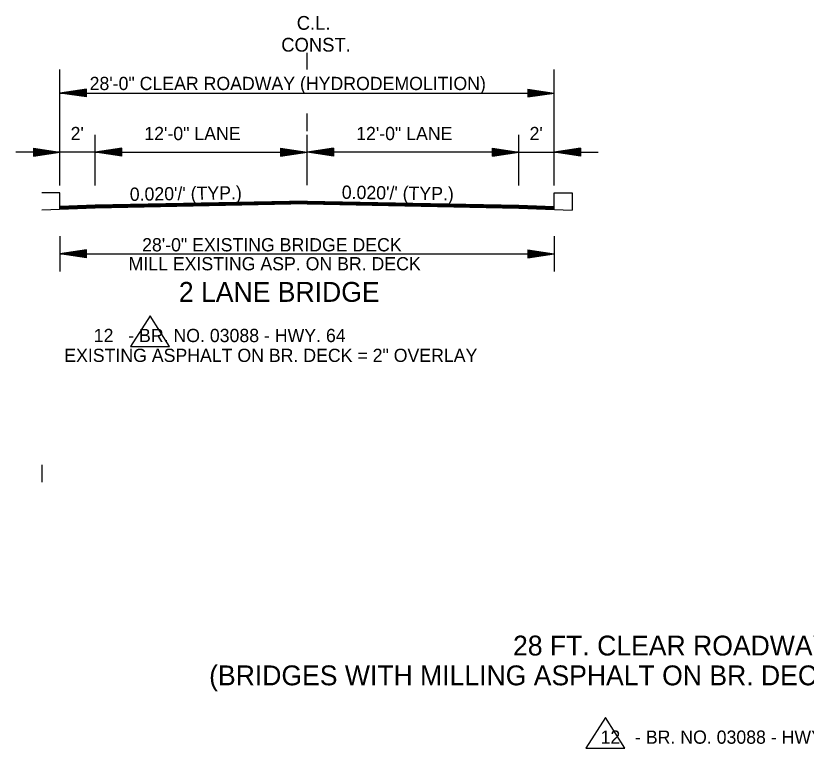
# Model space of a CAD drawing. Extents: x 542112 to 1930787, y -1968972 to 596640.
# Drawn here: x 544325.2 to 544772.9, y -1957025.2 to -1956610.4 of the extents above; entities that cross this region are included whole.
import ezdxf

# ---------------------------------------------------------------- set-up
doc = ezdxf.new("R2010")
doc.units = 0
doc.layers.add('R_Border', color=7, linetype='Continuous')
doc.layers.add('R_Draft', color=7, linetype='Continuous')

msp = doc.modelspace()

# ---------------------------------------------------------------- linework, layer by layer
at = {"layer": 'R_Border'}
for p, q in [((544350.18, -1956710.76), (544340.02, -1956710.76)), ((544350.18, -1956720.17), (544350.18, -1956710.76)), ((544630.18, -1956720.17), (544630.18, -1956710.76)), ((544630.18, -1956710.76), (544640.35, -1956710.76)), ((544640.35, -1956710.76), (544640.35, -1956720.57)), ((544401.25, -1956780.4), (544390.21, -1956797.7)), ((544412.29, -1956797.7), (544401.25, -1956780.4)), ((544390.21, -1956797.7), (544412.29, -1956797.7)), ((544340.02, -1956864.65), (544340.02, -1956874.46)), ((544659.17, -1957007.87), (544648.13, -1957025.17)), ((544670.21, -1957025.17), (544659.17, -1957007.87)), ((544648.13, -1957025.17), (544670.21, -1957025.17))]:
    msp.add_line(p, q, dxfattribs=at)
at = {"layer": 'R_Draft'}
for p, q in [((544490.18, -1956640.74), (544490.18, -1956631.43)), ((544350.18, -1956706.52), (544350.18, -1956640.78)), ((544630.18, -1956706.52), (544630.18, -1956640.78)), ((544365.18, -1956651.9), (544350.18, -1956654.15)), ((544350.18, -1956654.15), (544630.18, -1956654.15)), ((544365.18, -1956656.4), (544350.18, -1956654.15)), ((544365.18, -1956652.28), (544352.69, -1956654.15)), ((544365.18, -1956656.03), (544352.69, -1956654.15)), ((544365.18, -1956652.66), (544355.27, -1956654.15)), ((544365.18, -1956655.65), (544355.27, -1956654.15)), ((544365.18, -1956653.04), (544357.77, -1956654.15)), ((544365.18, -1956655.27), (544357.77, -1956654.15)), ((544365.18, -1956653.42), (544360.31, -1956654.15)), ((544365.18, -1956654.88), (544360.31, -1956654.15)), ((544365.18, -1956653.8), (544362.81, -1956654.15)), ((544365.18, -1956654.51), (544362.81, -1956654.15)), ((544365.18, -1956656.4), (544365.18, -1956651.9)), ((544615.18, -1956651.9), (544630.18, -1956654.15)), ((544615.18, -1956651.9), (544615.18, -1956656.4)), ((544615.18, -1956652.28), (544627.68, -1956654.15)), ((544615.18, -1956652.66), (544625.1, -1956654.15)), ((544615.18, -1956653.04), (544622.6, -1956654.15)), ((544615.18, -1956653.43), (544620.06, -1956654.15)), ((544615.18, -1956653.8), (544617.55, -1956654.15)), ((544615.18, -1956656.4), (544630.18, -1956654.15)), ((544615.18, -1956654.89), (544620.06, -1956654.15)), ((544615.18, -1956655.65), (544625.1, -1956654.15)), ((544615.18, -1956656.03), (544627.68, -1956654.15)), ((544615.18, -1956655.27), (544622.6, -1956654.15)), ((544615.18, -1956654.51), (544617.55, -1956654.15)), ((544490.18, -1956675.67), (544490.18, -1956665.8)), ((544370.18, -1956706.52), (544370.18, -1956677.8)), ((544490.18, -1956706.35), (544490.18, -1956677.8)), ((544610.18, -1956706.52), (544610.18, -1956677.8)), ((544335.18, -1956685.44), (544350.18, -1956687.69)), ((544335.18, -1956685.44), (544335.18, -1956689.94)), ((544335.18, -1956685.82), (544347.68, -1956687.69)), ((544385.18, -1956685.44), (544370.18, -1956687.69)), ((544385.18, -1956685.82), (544372.69, -1956687.69)), ((544385.18, -1956689.94), (544385.18, -1956685.44)), ((544475.18, -1956685.44), (544490.18, -1956687.69)), ((544475.18, -1956685.44), (544475.18, -1956689.94)), ((544475.18, -1956685.82), (544487.68, -1956687.69)), ((544505.18, -1956685.44), (544490.18, -1956687.69)), ((544505.18, -1956685.82), (544492.69, -1956687.69)), ((544505.18, -1956685.44), (544505.18, -1956689.94)), ((544595.18, -1956685.44), (544610.18, -1956687.69)), ((544595.18, -1956689.94), (544595.18, -1956685.44)), ((544595.18, -1956685.82), (544607.68, -1956687.69)), ((544645.18, -1956685.44), (544630.18, -1956687.69)), ((544645.18, -1956685.82), (544632.69, -1956687.69)), ((544645.18, -1956685.44), (544645.18, -1956689.94)), ((544350.18, -1956687.69), (544325.18, -1956687.69)), ((544335.18, -1956686.2), (544345.1, -1956687.69)), ((544335.18, -1956686.57), (544342.6, -1956687.69)), ((544335.18, -1956686.96), (544340.06, -1956687.69)), ((544335.18, -1956687.34), (544337.55, -1956687.69)), ((544335.18, -1956689.94), (544350.18, -1956687.69)), ((544335.18, -1956688.43), (544340.06, -1956687.69)), ((544335.18, -1956689.18), (544345.1, -1956687.69)), ((544335.18, -1956689.57), (544347.68, -1956687.69)), ((544335.18, -1956688.81), (544342.6, -1956687.69)), ((544335.18, -1956688.04), (544337.55, -1956687.69)), ((544370.18, -1956687.69), (544350.18, -1956687.69)), ((544385.18, -1956689.94), (544370.18, -1956687.69)), ((544370.18, -1956687.69), (544490.18, -1956687.69)), ((544385.18, -1956689.57), (544372.69, -1956687.69)), ((544385.18, -1956686.2), (544375.27, -1956687.69)), ((544385.18, -1956689.18), (544375.27, -1956687.69)), ((544385.18, -1956686.57), (544377.77, -1956687.69)), ((544385.18, -1956688.81), (544377.77, -1956687.69)), ((544385.18, -1956686.96), (544380.31, -1956687.69)), ((544385.18, -1956688.42), (544380.31, -1956687.69)), ((544385.18, -1956687.34), (544382.81, -1956687.69)), ((544385.18, -1956688.04), (544382.81, -1956687.69)), ((544475.18, -1956686.2), (544485.1, -1956687.69)), ((544475.18, -1956686.57), (544482.6, -1956687.69)), ((544475.18, -1956686.96), (544480.06, -1956687.69)), ((544475.18, -1956687.34), (544477.55, -1956687.69)), ((544475.18, -1956689.94), (544490.18, -1956687.69)), ((544475.18, -1956688.43), (544480.06, -1956687.69)), ((544475.18, -1956689.18), (544485.1, -1956687.69)), ((544475.18, -1956689.57), (544487.68, -1956687.69)), ((544475.18, -1956688.81), (544482.6, -1956687.69)), ((544475.18, -1956688.04), (544477.55, -1956687.69)), ((544610.18, -1956687.69), (544490.18, -1956687.69)), ((544505.18, -1956689.94), (544490.18, -1956687.69)), ((544505.18, -1956689.57), (544492.69, -1956687.69)), ((544505.18, -1956686.2), (544495.27, -1956687.69)), ((544505.18, -1956689.18), (544495.27, -1956687.69)), ((544505.18, -1956686.57), (544497.77, -1956687.69)), ((544505.18, -1956688.81), (544497.77, -1956687.69)), ((544505.18, -1956686.96), (544500.31, -1956687.69)), ((544505.18, -1956688.43), (544500.31, -1956687.69)), ((544505.18, -1956687.34), (544502.81, -1956687.69)), ((544505.18, -1956688.04), (544502.81, -1956687.69)), ((544595.18, -1956686.2), (544605.1, -1956687.69)), ((544595.18, -1956686.57), (544602.6, -1956687.69)), ((544595.18, -1956686.96), (544600.06, -1956687.69)), ((544595.18, -1956687.34), (544597.55, -1956687.69)), ((544595.18, -1956689.94), (544610.18, -1956687.69)), ((544595.18, -1956688.42), (544600.06, -1956687.69)), ((544595.18, -1956689.18), (544605.1, -1956687.69)), ((544595.18, -1956689.57), (544607.68, -1956687.69)), ((544595.18, -1956688.81), (544602.6, -1956687.69)), ((544595.18, -1956688.04), (544597.55, -1956687.69)), ((544610.18, -1956687.69), (544630.18, -1956687.69)), ((544645.18, -1956689.94), (544630.18, -1956687.69)), ((544630.18, -1956687.69), (544655.18, -1956687.69)), ((544645.18, -1956689.57), (544632.69, -1956687.69)), ((544645.18, -1956686.2), (544635.27, -1956687.69)), ((544645.18, -1956689.18), (544635.27, -1956687.69)), ((544645.18, -1956686.57), (544637.77, -1956687.69)), ((544645.18, -1956688.81), (544637.77, -1956687.69)), ((544645.18, -1956686.96), (544640.31, -1956687.69)), ((544645.18, -1956688.43), (544640.31, -1956687.69)), ((544645.18, -1956687.34), (544642.81, -1956687.69)), ((544645.18, -1956688.04), (544642.81, -1956687.69)), ((544490.18, -1956715.3), (544370.18, -1956717.7)), ((544490.19, -1956715.6), (544370.18, -1956718)), ((544490.2, -1956715.9), (544370.18, -1956718.3)), ((544490.2, -1956716.2), (544370.18, -1956718.6)), ((544490.21, -1956716.5), (544370.18, -1956718.9)), ((544490.21, -1956716.8), (544370.18, -1956719.2)), ((544490.22, -1956716.97), (544370.18, -1956719.37)), ((544490.15, -1956716.8), (544610.18, -1956719.2)), ((544490.15, -1956716.97), (544610.18, -1956719.37)), ((544490.16, -1956716.5), (544610.18, -1956718.9)), ((544490.17, -1956715.9), (544610.18, -1956718.3)), ((544490.17, -1956716.2), (544610.18, -1956718.6)), ((544490.18, -1956715.3), (544610.18, -1956717.7)), ((544490.18, -1956715.6), (544610.18, -1956718)), ((544370.18, -1956719.37), (544340.02, -1956720.57)), ((544370.18, -1956717.7), (544350.18, -1956718.5)), ((544370.18, -1956718), (544350.18, -1956718.8)), ((544370.18, -1956718.3), (544350.18, -1956719.1)), ((544370.18, -1956718.6), (544350.18, -1956719.4)), ((544370.18, -1956718.9), (544350.18, -1956719.7)), ((544370.18, -1956719.2), (544350.18, -1956720)), ((544610.18, -1956717.7), (544630.18, -1956718.5)), ((544610.18, -1956718), (544630.18, -1956718.8)), ((544610.18, -1956718.3), (544630.18, -1956719.1)), ((544610.18, -1956718.6), (544630.18, -1956719.4)), ((544610.18, -1956718.9), (544630.18, -1956719.7)), ((544610.18, -1956719.2), (544630.18, -1956720)), ((544610.18, -1956719.37), (544640.35, -1956720.57)), ((544350.18, -1956735.15), (544350.18, -1956755.15)), ((544630.18, -1956735.15), (544630.18, -1956755.15)), ((544365.18, -1956742.9), (544350.18, -1956745.15)), ((544365.18, -1956743.28), (544352.69, -1956745.15)), ((544365.18, -1956743.66), (544355.27, -1956745.15)), ((544365.18, -1956744.04), (544357.77, -1956745.15)), ((544365.18, -1956747.4), (544365.18, -1956742.9)), ((544615.18, -1956742.9), (544630.18, -1956745.15)), ((544615.18, -1956742.9), (544615.18, -1956747.4)), ((544615.18, -1956743.28), (544627.68, -1956745.15)), ((544615.18, -1956743.66), (544625.1, -1956745.15)), ((544615.18, -1956744.04), (544622.6, -1956745.15)), ((544350.18, -1956745.15), (544630.18, -1956745.15)), ((544365.18, -1956747.4), (544350.18, -1956745.15)), ((544365.18, -1956747.03), (544352.69, -1956745.15)), ((544365.18, -1956746.65), (544355.27, -1956745.15)), ((544365.18, -1956746.27), (544357.77, -1956745.15)), ((544365.18, -1956744.42), (544360.31, -1956745.15)), ((544365.18, -1956745.88), (544360.31, -1956745.15)), ((544365.18, -1956744.8), (544362.81, -1956745.15)), ((544365.18, -1956745.51), (544362.81, -1956745.15)), ((544615.18, -1956744.43), (544620.06, -1956745.15)), ((544615.18, -1956744.8), (544617.55, -1956745.15)), ((544615.18, -1956747.4), (544630.18, -1956745.15)), ((544615.18, -1956745.89), (544620.06, -1956745.15)), ((544615.18, -1956746.65), (544625.1, -1956745.15)), ((544615.18, -1956747.03), (544627.68, -1956745.15)), ((544615.18, -1956746.27), (544622.6, -1956745.15)), ((544615.18, -1956745.51), (544617.55, -1956745.15))]:
    msp.add_line(p, q, dxfattribs=at)

# ---------------------------------------------------------------- texts
for s, height, p in [('C.L.', 7.8, (544484.34, -1956618.34)), ('CONST.', 7.8, (544475.56, -1956630.71)), ('28\'-0" CLEAR ROADWAY (HYDRODEMOLITION)', 7.5, (544367, -1956652.48)), ("2'", 7.5, (544356.23, -1956680.83)), ('12\'-0" LANE', 7.5, (544398, -1956680.83)), ('12\'-0" LANE', 7.5, (544518, -1956680.83)), ("2'", 7.5, (544616.23, -1956680.83)), ('28\'-0" EXISTING BRIDGE DECK', 7.5, (544396.74, -1956743.83)), ('MILL EXISTING ASP. ON BR. DECK', 7.5, (544389.06, -1956754.56)), ('2 LANE BRIDGE', 11.25, (544417.56, -1956772.4)), ('      12   - BR. NO. 03088 - HWY. 64', 7.5, (544352.63, -1956795.2)), ('EXISTING ASPHALT ON BR. DECK = 2" OVERLAY', 7.5, (544352.63, -1956806.45)), ('28 FT. CLEAR ROADWAY BRIDGE - HYDRODEMOLITION', 11.25, (544606.87, -1956972.68)), ('(BRIDGES WITH MILLING ASPHALT ON BR. DECK, ROADWAY TRANSITIONS, AND NEW GUARDRAIL)', 11.25, (544434.71, -1956989.56)), ('12   - BR. NO. 03088 - HWY. 64: EXISTING ASPHALT ON BR. DECK = 2" OVERLAY', 7.5, (544656.46, -1957022.66))]:
    msp.add_text(s, height=height, dxfattribs=at).set_placement(p)
for rotation, p in [(0.8719, (544389.8, -1956715.25)), (359.1281, (544509.79, -1956714.02))]:
    msp.add_text("0.020'/' (TYP.)", height=7.5, rotation=rotation, dxfattribs=at).set_placement(p)

doc.saveas('drawing.dxf')
